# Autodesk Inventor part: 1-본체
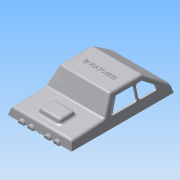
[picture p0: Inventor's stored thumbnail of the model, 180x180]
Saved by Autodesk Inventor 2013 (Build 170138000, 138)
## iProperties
Created: 2015-06
Part Number: 1-본체
Material: ABS 플라스틱
Document SubType Name: Modeling
Designer: Administrator
Density: 7.85 g/cm^3
Mass: 250.813 g
Surface Area: 309.313 cm^2
Volume: 31.9507 cm^3
Author: Administrator
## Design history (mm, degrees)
sketch "스케치1"
  geometry: L1 (0, 0)-(122, 0); L2 (0, 0)-(2.412, 9); L3 (42, 11.075)-(53.826, 30); L4 (53.826, 30)-(92, 30); L5 (92, 30)-(119.321, 10); L6 (119.321, 10)-(122, 0); L7 (2.412, 9)-(42, 11.075)
  constraints: 14 end point, 1 horizontal, 1 parallel
  dimensions: "d1" = 105 deg angle of L1 L2; "d2" = 105 deg angle of L1 L6; "d5" = 30 distance between parallel lines of L1 L4; "d6" = 20 distance from line of L5.end L4; "d10" = 3 deg angle of L1 L7; "d11" = 125 deg angle of L7 L3; "d12" = 42 horizontal distance of L3.start L1.start; "d13" = 9 vertical distance of L1.start L2.end; "d26" = 122 distance of L1.start L1.end; "d40" = 30 horizontal distance of L1.end L4.end
extrude "돌출1" new body sketch "스케치1" stored distance "d14" = 76; taper "d15" = 0 deg
sketch "스케치2"
  geometry: L1 (28.121, 51)-(8.121, 51); L2 (8.121, 51)-(8.121, 25); L3 (8.121, 25)-(28.121, 25); L4 (28.121, 25)-(28.121, 51); L5 (-2.879, 0)-(-2.879, 76) reference; 2 further points
  constraints: 8 end point, 2 parallel, 1 horizontal, 1 horizontal alignment, 1 midpoint, 1 perpendicular
  dimensions: "d16" = 20 distance of L1.start L1.end; "d18" = 26 distance of L3.end L1.start; "d19" = 11 distance between parallel lines of L5 L2
extrude "돌출2" join sketch "스케치2" distance "d20" = 5; taper "d21" = 0 deg
sketch "스케치4"
  geometry: L1 (30, -38)-(30, 38) reference; L2 (0, 38)-(0, -38) reference; L3 (30, 38)-(11.075, 38) reference; L4 (11.075, 38)-(9, 38) reference; L5 (9, 38)-(0, 38) reference; L6 (11.075, -38)-(30, -38) reference; L7 (0, -38)-(9, -38) reference; L8 (9, -38)-(11.075, -38) reference; L9 (0, 38)-(30, 29.962); L10 (0, -38)-(30, -29.962); 1 further point
  constraints: 4 end point, 2 point on line
  dimensions: "d27" = 105 deg angle of L2 L9; "d28" = 105 deg angle of L2 L10
extrude "돌출3" cut sketch "스케치4" distance "d29" = 130; taper "d30" = 0 deg
sketch "스케치7"
  geometry: 1 further point
feature "쉘2" dims "d61" = 2
sketch "스케치11"
  geometry: L1 (119.929, -2.071)-(119.929, -73.929) reference; L2 (119.929, -73.929)-(2.071, -73.929) reference; L3 (2.071, -73.929)-(2.071, -2.071) reference; L4 (2.071, -2.071)-(119.929, -2.071) reference; L5 (122, -76)-(122, 0) reference; L6 (0, 0)-(122, 0) reference; L7 (0, 0)-(0, -76) reference; L8 (122, -76)-(0, -76) reference; L9 (1, -1)-(121, -1); L10 (121, -1)-(121, -75); L11 (121, -75)-(1, -75); L12 (1, -75)-(1, -1); 1 further point
  constraints: 8 end point, 2 parallel, 1 horizontal, 1 perpendicular
  dimensions: "d77" = 1 distance between parallel lines of L10 L5; "d78" = 1 distance between parallel lines of L9 L6; "d79" = 1 distance between parallel lines of L12 L7; "d80" = 1 distance between parallel lines of L11 L8
extrude "돌출8" join sketch "스케치11" distance "d81" = 1; taper "d82" = 0 deg
sketch "스케치12"
  geometry: L1 (42, 11.075)-(53.826, 30) reference; L2 (53.826, 30)-(92, 30) reference; L3 (92, 30)-(119.321, 10) reference; L4 (47.224, 10)-(56.597, 25); L5 (90.365, 25)-(110.856, 10); L6 (56.597, 25)-(81.224, 25); L7 (81.224, 25)-(81.224, 10); L8 (81.224, 10)-(47.224, 10); L9 (90.365, 25)-(82.856, 25); L10 (82.856, 25)-(82.856, 10); L11 (82.856, 10)-(110.856, 10); 1 further point
  constraints: 16 end point, 4 parallel, 2 perpendicular
  dimensions: "d84" = 5 distance between parallel lines of L3 L5; "d85" = 5 distance between parallel lines of L4 L1; "d86" = 5 distance between parallel lines of L6 L2; "d87" = 5 distance between parallel lines of L9 L2; "d88" = 34 distance of L7.end L4.start; "d89" = 28 distance of L10.end L5.end; "d90" = 15 vertical distance of L4.start L4.end; "d91" = 15 vertical distance of L5.start L5.end
extrude "돌출9" cut sketch "스케치12" stored distance "d92" = 1; taper "d93" = 0 deg
node "작업 평면1"
sketch "스케치13"
  geometry: A1 r 4 centre (0, -10) between (0, -6) and (0, -14); A2 r 4 centre (0, -21) between (0, -17) and (0, -25); A3 r 4 centre (0, 10) between (0, 14) and (0, 6); A4 r 4 centre (0, 21) between (0, 25) and (0, 17); 3 further points
  constraints: 8 point on circle, 4 centre point, 3 equal radius, 13 other
  dimensions: "d95" = 4 radius of A2; "d97" = 20 distance of A3.centre A1.centre; "d98" = 11 distance of A1.centre A2.centre; "d99" = 11 distance of A4.centre A3.centre; "d100" = 10 distance of point (0, 0) A3.centre
extrude "돌출10" join sketch "스케치13" stored distance "d101" = 1; taper "d102" = 0 deg
sketch "스케치14"
  geometry: L1 (68.174, 8.038)-(68.174, -67.962) reference; 2 further points
  constraints: 1 horizontal alignment, 1 other
  dimensions: "d103" = 50 distance from line of L1 point (18.174, -29.962)
feature "엠보싱1" sketch "스케치14" dims "d16" = 20, "d18" = 26, "d19" = 11, "d104" = 0.5, "d105" = 0
sketch "스케치15"
  geometry: L1 (122, 0)-(122, 76) reference; L2 (1, 75)-(1, 1) reference; C1 r 3 at (21, 38); C2 r 3 at (61, 60); C3 r 3 at (61, 16); C4 r 3 at (101, 38); 2 further points
  constraints: 4 centre point, 3 equal radius, 2 horizontal alignment, 1 midpoint, 1 vertical alignment
  dimensions: "d106" = 6 diameter of C1; "d108" = 21 distance from line of L1 C4.centre; "d109" = 40 horizontal distance of C4.centre C2.centre; "d110" = 40 horizontal distance of C2.centre C1.centre; "d111" = 44 distance of C3.centre C2.centre; "d112" = 22 vertical distance of C3.centre C1.centre
extrude "돌출11" join sketch "스케치15" stored distance "d113" = 1; taper "d114" = 2 deg
sketch "스케치16"
  geometry: L1 (30.494, 10.472)-(30.232, 15.465) reference; L2 (10.521, 9.425)-(10.259, 14.418) reference; L3 (10.259, 14.418)-(30.232, 15.465) reference; L4 (30.494, 10.472)-(28.415, 15.37); L5 (10.521, 9.425)-(12.077, 14.513); L6 (2.412, 9)-(42, 11.075) reference; 1 further point
  constraints: 4 end point, 2 point on line
  dimensions: "d115" = 70 deg angle of L6 L4; "d116" = 70 deg angle of L5 L6
extrude "돌출12" cut sketch "스케치16" stored distance "d117" = 1; taper "d118" = 0 deg
sketch "스케치18"
  geometry: L1 (0, 0)-(122, 0) reference; L2 (24, 0)-(24.46, 13.16) reference; L3 (18, 0)-(17.553, 12.798) reference; L4 (12.361, 12.526)-(28.339, 13.363) reference; L5 (14.653, 12.646)-(16.53, 2); L6 (16.53, 2)-(25.47, 2); L7 (25.47, 2)-(27.465, 13.317); L8 (21, 2)-(21, 12.978)
  constraints: 8 end point, 3 point on line, 1 midpoint, 1 parallel, 1 perpendicular
  dimensions: "d124" = 3 distance from line of L3.start L8; "d125" = 20 deg angle of L5 L7; "d126" = 80 deg angle of L6 L5; "d127" = 2 distance between parallel lines of L1 L6; "d128" = 11.31711 vertical distance of L6.end L7.end
extrude "돌출13" join sketch "스케치18" stored distance "d129" = 2; taper "d130" = 0 deg
sketch "스케치19"
  geometry: L1 (0, 0)-(2, 0) reference; L2 (2, 10.81)-(2, 0) reference; L3 (0, 10.81)-(2, 10.81) reference; L4 (0, 0)-(0, 10.81) reference; L5 (0, 0)-(-0.472, 10.81); L6 (-0.472, 10.81)-(2.472, 10.81); L7 (2.472, 10.81)-(2, 0); 1 further point
  constraints: 6 end point, 1 horizontal, 1 point on line
  dimensions: "d131" = 5 deg angle of L7 L5; "d132" = 87.5 deg angle of L1 L5
extrude "돌출14" join sketch "스케치19" stored distance "d133" = 2; taper "d134" = 0 deg
sketch "스케치20"
  geometry: L1 (0, 0)-(2, 0) reference; L2 (0, -11.492)-(0, 0) reference; L3 (2, -11.492)-(0, -11.492) reference; L4 (2, 0)-(2, -11.492) reference; L5 (0, -11.492)-(-0.502, 0); L6 (-0.502, 0)-(2.502, 0); L7 (2.502, 0)-(2, -11.492); 1 further point
  constraints: 6 end point, 1 horizontal, 1 point on line
  dimensions: "d135" = 87.5 deg angle of L3 L5; "d136" = 5 deg angle of L7 L5
extrude "돌출15" join sketch "스케치20" stored distance "d137" = 2; taper "d138" = 0 deg
sketch "스케치22"
  geometry: L1 (91.346, 28)-(117.571, 8.802) reference; L2 (92, 30)-(119.321, 10) reference; L3 (0, 0)-(122, 0) reference; L4 (93.344, 2)-(108.656, 2); L5 (108.656, 2)-(111.124, 16); L6 (54.934, 28)-(91.346, 28) reference; L7 (93.344, 2)-(88.407, 30); L8 (101, 2)-(101, 23.412); L9 (98, 0)-(97.171, 23.736) reference; L10 (104, 0)-(104.638, 18.27) reference; L11 (53.826, 30)-(92, 30) reference
  constraints: 8 end point, 3 point on line, 1 midpoint, 1 parallel, 1 perpendicular
  dimensions: "d139" = 3 horizontal distance of L9.start L8.start; "d140" = 80 deg angle of L4 L7; "d141" = 20 deg angle of L5 L7; "d142" = 2 distance between parallel lines of L3 L4; "d143" = 14 vertical distance of L4.end L5.end
extrude "돌출16" join sketch "스케치22" stored distance "d144" = 2; taper "d145" = 0 deg
sketch "스케치23"
  geometry: L1 (0, 0)-(2, 0) reference; L2 (0, -26.401)-(0, 0) reference; L3 (0, -26.401)-(2, -26.401) reference; L4 (2, 0)-(2, -26.401) reference; L5 (0, -26.401)-(-1.153, 0); L6 (-1.153, 0)-(3.153, 0); L7 (3.153, 0)-(2, -26.401); 2 further points
  constraints: 6 end point, 2 midpoint, 1 equal length, 1 perpendicular
  dimensions: "d146" = 87.5 deg angle of L3 L5
extrude "돌출17" join sketch "스케치23" stored distance "d147" = 2; taper "d148" = 0 deg
sketch "스케치24"
  geometry: L1 (0, 0)-(2, 0) reference; L2 (0, -11.987)-(0, 0) reference; L3 (2, -11.987)-(0, -11.987) reference; L4 (2, 0)-(2, -11.987) reference; L5 (0, -11.987)-(-0.523, 0); L6 (-0.523, 0)-(2.523, 0); L7 (2.523, 0)-(2, -11.987); 1 further point
  constraints: 6 end point, 1 equal length, 1 horizontal, 1 point on line
  dimensions: "d149" = 87.5 deg angle of L3 L5
extrude "돌출18" join sketch "스케치24" stored distance "d150" = 2; taper "d151" = 0 deg
node "작업 평면2"
sketch "스케치25"
  geometry: L1 (0, 0)-(122, 0) reference; L2 (42, 11.075)-(53.826, 30) reference; L3 (53.826, 30)-(92, 30) reference; L4 (58, 0)-(57.022, 28) reference; L5 (64, 0)-(64.978, 28) reference; L6 (58, 0)-(52.956, 28.608); L7 (64, 0)-(69.29, 30)
  constraints: 4 end point, 2 point on line
  dimensions: "d153" = 80 deg angle of L1 L6; "d154" = 80 deg angle of L1 L7
extrude "돌출19" join sketch "스케치25" stored distance "d155" = 2; taper "d156" = 0 deg
sketch "스케치26"
  geometry: L1 (0, 0)-(2, 0) reference; L2 (0, -26.06)-(0, 0) reference; L3 (0, -26.06)-(2, -26.06) reference; L4 (2, 0)-(2, -26.06) reference; L5 (0, -26.06)-(-1.138, 0); L6 (-1.138, 0)-(3.138, 0); L7 (3.138, 0)-(2, -26.06); 2 further points
  constraints: 6 end point, 2 midpoint, 1 equal length, 1 perpendicular
  dimensions: "d157" = 87.5 deg angle of L3 L5
extrude "돌출20" join sketch "스케치26" stored distance "d158" = 2; taper "d159" = 0 deg
node "작업 평면3"
sketch "스케치27"
  geometry: L1 (0, 0)-(2, 0) reference; L2 (0, -28.432)-(0, 0) reference; L3 (2, -28.432)-(0, -28.432) reference; L4 (2, 0)-(2, -28.432) reference; L5 (0, -28.432)-(-1.241, 0); L6 (-1.241, 0)-(3.241, 0); L7 (3.241, 0)-(2, -28.432); 2 further points
  constraints: 6 end point, 2 midpoint, 1 equal length, 1 perpendicular
  dimensions: "d161" = 87.5 deg angle of L3 L5
extrude "돌출21" join sketch "스케치27" stored distance "d162" = 2; taper "d163" = 0 deg
fillet "모깎기1" dims "d164" = 3
chamfer "모따기1" distance "d165" = 1; stored, may be unused: second distance "d166" = 2, angle "d167" = 45 deg
fillet "모깎기2" dims "d168" = 3
fillet "모깎기3" dims "d169" = 3
fillet "모깎기4" dims "d170" = 3
fillet "모깎기5" dims "d171" = 3
fillet "모깎기6" dims "d172" = 3
node "솔리드1"
mirror "대칭1"
other parameters: "d94" = -2, "d152" = 22, "d160" = -2
